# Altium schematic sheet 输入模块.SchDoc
size A4; Address1: 张三; Address2: 202311001; Address3: 23应用电子1班
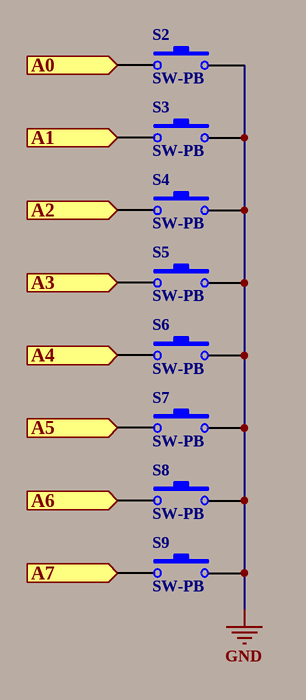
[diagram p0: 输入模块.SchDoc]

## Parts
S2  SW-PB  [轻触开关]
S3  SW-PB  [轻触开关]
S4  SW-PB  [轻触开关]
S5  SW-PB  [轻触开关]
S6  SW-PB  [轻触开关]
S7  SW-PB  [轻触开关]
S8  SW-PB  [轻触开关]
S9  SW-PB  [轻触开关]

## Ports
A0 (out), A1 (out), A2 (out), A3 (out), A4 (out), A5 (out), A6 (out), A7 (out)

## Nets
GND: S2.2 S3.2 S4.2 S5.2 S6.2 S7.2 S8.2 S9.2
A0: S2.1 ; port A0
A1: S3.1 ; port A1
A2: S4.1 ; port A2
A3: S5.1 ; port A3
A4: S6.1 ; port A4
A5: S7.1 ; port A5
A6: S8.1 ; port A6
A7: S9.1 ; port A7

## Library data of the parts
S2-S9 = SW-PB: Switch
